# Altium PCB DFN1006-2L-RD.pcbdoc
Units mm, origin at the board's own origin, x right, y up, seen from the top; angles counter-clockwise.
Board outline 14.4 x 13.7 mm, 2 copper layers (Top Layer, Bottom Layer), stack 0.07 mm thick; 1 components, 0 nets, 2 pads, 0 vias.
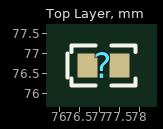
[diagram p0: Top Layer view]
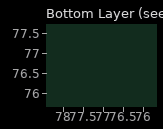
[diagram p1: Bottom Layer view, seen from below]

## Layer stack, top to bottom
Top Solder Mask Layer: solder mask 0.01, Dk 3.3
Top Layer: signal copper 0.035
Bottom Layer: signal copper 0.035
Bottom Solder Mask Layer: solder mask 0.01, Dk 3.3

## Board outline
84.25,69.85 69.85,69.85 69.85,83.55 84.25,83.55

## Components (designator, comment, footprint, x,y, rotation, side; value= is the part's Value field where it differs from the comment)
? "DFN1006-2L-RD" DFN1006-2L-RD 77.1,76.7 r0 top

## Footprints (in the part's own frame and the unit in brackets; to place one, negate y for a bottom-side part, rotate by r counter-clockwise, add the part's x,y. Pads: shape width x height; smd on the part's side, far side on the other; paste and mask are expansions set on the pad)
DFN1006-2L-RD [mm]
  rect 0.5x0.6 smd paste+0 mask+0.051: 1(-0.4,0) 2(0.4,0)
  silkscreen extent -0.9,-0.5 0.8,0.5

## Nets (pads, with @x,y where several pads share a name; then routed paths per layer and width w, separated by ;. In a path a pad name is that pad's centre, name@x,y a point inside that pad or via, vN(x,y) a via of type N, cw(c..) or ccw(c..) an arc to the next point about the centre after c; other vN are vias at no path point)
pads on no net: ?.1 ?.2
